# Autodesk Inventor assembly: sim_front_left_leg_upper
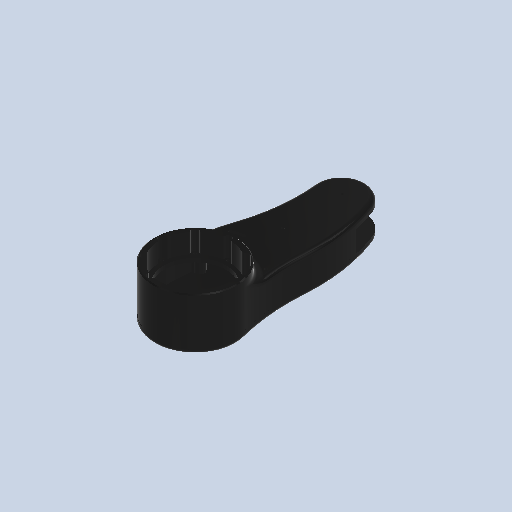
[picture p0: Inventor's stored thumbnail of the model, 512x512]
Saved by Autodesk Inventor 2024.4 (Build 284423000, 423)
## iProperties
Created: 2026-01
Part Number: sim_front_left_leg_upper
Document SubType Name: Assembly
Designer: AdminForWorker
Title: hind_right_leg_upper v2
Author: AdminForWorker
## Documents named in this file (3)
- c:\worker\convert-fusion-r06-cosv3\tmp\job-1\57\temp\files\8ade0e93-a5d6-43ff-bc71-8f783fe6c897\023ef48b-aaca-41b3-b704-eec730ed5eb3.iam
- c:\worker\convert-fusion-r06-cosv3\tmp\job-1\57\temp\files\8ade0e93-a5d6-43ff-bc71-8f783fe6c897\leg_upper_inner.ipt
- c:\worker\convert-fusion-r06-cosv3\tmp\job-1\57\temp\files\8ade0e93-a5d6-43ff-bc71-8f783fe6c897\leg_upper_outer.ipt
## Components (2 placed, 2 different names)
1. leg_upper_inner:1
2. leg_upper_outer:1
